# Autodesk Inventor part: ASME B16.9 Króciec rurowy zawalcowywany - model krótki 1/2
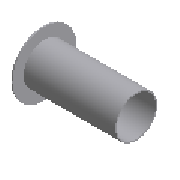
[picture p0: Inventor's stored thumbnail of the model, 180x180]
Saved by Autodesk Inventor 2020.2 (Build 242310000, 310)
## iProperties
Manager: www.cadconsulting.pl
Company: Fabian Stasiak CAD Consulting
IsCustomPart: 0
NAME: PIPING: ASME B16.9 Lap Joint Stub End - Short Pattern
DATA: <meta><inlinegroups number="1" deflen="5.00888"></inlinegroups><connections number="2"></connections><angles><a>3.14159265358979</a></angles></meta>
Created: 2014-02
Part Number: ASME B16.9 Króciec rurowy zawalcowywany - model krótki 1/2
Material: Stal kuta
Description: ASME B16.9 Króciec rurowy zawalcowywany - model krótki ze stali kutej .calowy
Document SubType Name: Modeling
Standard: ASME B16.9
Designer: F.Stasiak
Standard Revision: 2003
Standards Organization: ANSI
Language: pl-PL
Size Designation: 1/2
Categories: <MemberInstance><Categories><Category DisplayName="Rury cienko- i grubościenne" InternalName="4347fa0f-2144-441d-94cd-e3e15c92b736" Mnemonic="TUBEANDPIPE"><Cate
Density: 1 g/cm^3
Appearance: Stal
Catalog Web Link: www.expertbooks.pl
Author: F.Stasiak
Subject: Zbiór ćwiczeń. Autodesk Inventor 2020. Kurs Professional
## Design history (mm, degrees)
sketch "Sketch1"
  geometry: L1 (0, 0)-(-50.8, 0); L2 (0, 0)-(0, 10.274); L3 (0, 10.274)-(0, 17.526); L4 (0, 17.526)-(-1.105, 17.526); L5 (-1.105, 17.526)-(-1.105, 11.379); L6 (0, 10.274)-(-50.8, 10.274); L7 (-50.8, 10.274)-(-50.8, 11.379); L8 (-50.8, 11.379)-(-1.105, 11.379); L9 (-50.8, 10.274)-(-50.8, 0); C1 r 1.105 at (-1.105, 11.379); 1 further point
  constraints: 18 end point, 4 perpendicular, 2 coincident, 2 collinear, 2 parallel, 2 tangent, 1 centre point, 1 horizontal
  dimensions: "d0" = 50.8 distance of L1.start L1.end (= F1); "d1" = 20.5486 diameter of L6 L1 (= OD2); "d2" = 22.7584 diameter of L8 L1 (= OD); "d3" = 35.052 diameter of L4 L1 (= G)
revolve "Revolution1" sketch "Sketch1" stored, may be unused: angle "d16" = 90 deg
workaxis "Work Axis1"
workpoint "Work Point1"
workaxis "Work Axis2"
workpoint "Work Point2"
workaxis "Work Axis3"
workaxis "Work Axis4"
workpoint "Work Point3"
body "Solid1"
other parameters: "F1" = 50.8 [user parameter; used in 1 equation term], "OD" = 22.7584 [user parameter; used in 1 equation term], "G" = 35.052 [user parameter; used in 1 equation term], "R" = 3.048 [user parameter], "OD2" = 20.5486 [user parameter; used in 1 equation term], "Size_Designation" = 5 [user parameter]
